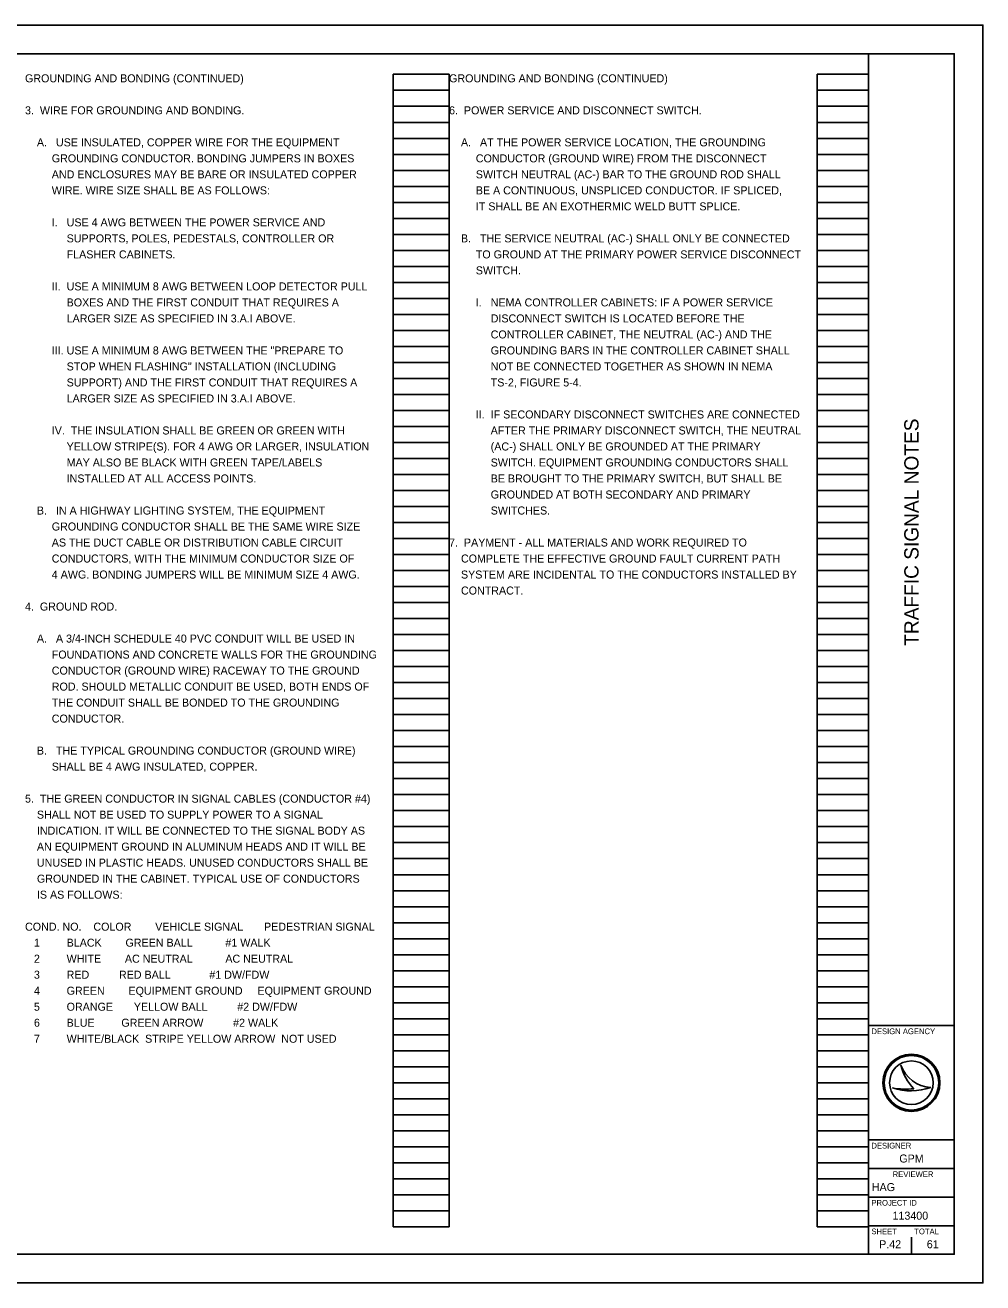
# Model space of a CAD drawing. Extents: x 0 to 34, y 0 to 22.
# Drawn here: x 17.24 to 34, y 0 to 22 of the extents above; entities that cross this region are included whole.
import ezdxf

# ---------------------------------------------------------------- set-up
doc = ezdxf.new("R2010")
doc.units = 0
for name, color, linetype in [('SH_Border', 7, 'Continuous'), ('SH_Cut_Line', 7, 'Continuous'), ('SH_Data', 7, 'Continuous'), ('SH_Text', 7, 'Continuous')]:
    doc.layers.add(name, color=color, linetype=linetype)

msp = doc.modelspace()

# ---------------------------------------------------------------- linework, layer by layer
at = {"layer": 'SH_Border'}
for p, q in [((32, 0.5), (32, 21.5)), ((32, 4.5), (33.5, 4.5)), ((32, 2.5), (33.5, 2.5)), ((32, 2), (33.5, 2)), ((32, 1.5), (33.5, 1.5)), ((32, 1), (33.5, 1))]:
    msp.add_line(p, q, dxfattribs=at)
msp.add_lwpolyline([(1.5, 21.5), (33.5, 21.5), (33.5, 0.5), (1.5, 0.5)], close=True, dxfattribs=at)
at = {"layer": 'SH_Cut_Line'}
msp.add_lwpolyline([(0, 0), (34, 0), (34, 22), (0, 22)], close=True, dxfattribs=at)
at = {"layer": 'SH_Data'}
for p, q in [((23.68, 0.98), (23.68, 21.14)), ((23.68, 21.14), (24.66, 21.14)), ((24.66, 0.98), (24.66, 21.14)), ((31.1, 0.98), (31.1, 21.14)), ((31.1, 21.14), (32, 21.14)), ((32, 0.98), (32, 21.14)), ((23.68, 20.86), (24.66, 20.86)), ((31.1, 20.86), (32, 20.86)), ((23.68, 20.58), (24.66, 20.58)), ((31.1, 20.58), (32, 20.58)), ((23.68, 20.3), (24.66, 20.3)), ((31.1, 20.3), (32, 20.3)), ((23.68, 20.02), (24.66, 20.02)), ((31.1, 20.02), (32, 20.02)), ((23.68, 19.74), (24.66, 19.74)), ((31.1, 19.74), (32, 19.74)), ((23.68, 19.46), (24.66, 19.46)), ((31.1, 19.46), (32, 19.46)), ((23.68, 19.18), (24.66, 19.18)), ((31.1, 19.18), (32, 19.18)), ((23.68, 18.9), (24.66, 18.9)), ((31.1, 18.9), (32, 18.9)), ((23.68, 18.62), (24.66, 18.62)), ((31.1, 18.62), (32, 18.62)), ((23.68, 18.34), (24.66, 18.34)), ((31.1, 18.34), (32, 18.34)), ((23.68, 18.06), (24.66, 18.06)), ((31.1, 18.06), (32, 18.06)), ((23.68, 17.78), (24.66, 17.78)), ((31.1, 17.78), (32, 17.78)), ((23.68, 17.5), (24.66, 17.5)), ((31.1, 17.5), (32, 17.5)), ((23.68, 17.22), (24.66, 17.22)), ((31.1, 17.22), (32, 17.22)), ((23.68, 16.94), (24.66, 16.94)), ((31.1, 16.94), (32, 16.94)), ((23.68, 16.66), (24.66, 16.66)), ((31.1, 16.66), (32, 16.66)), ((23.68, 16.38), (24.66, 16.38)), ((31.1, 16.38), (32, 16.38)), ((23.68, 16.1), (24.66, 16.1)), ((31.1, 16.1), (32, 16.1)), ((23.68, 15.82), (24.66, 15.82)), ((31.1, 15.82), (32, 15.82)), ((23.68, 15.54), (24.66, 15.54)), ((31.1, 15.54), (32, 15.54)), ((23.68, 15.26), (24.66, 15.26)), ((31.1, 15.26), (32, 15.26)), ((23.68, 14.98), (24.66, 14.98)), ((31.1, 14.98), (32, 14.98)), ((23.68, 14.7), (24.66, 14.7)), ((31.1, 14.7), (32, 14.7)), ((23.68, 14.42), (24.66, 14.42)), ((31.1, 14.42), (32, 14.42)), ((23.68, 14.14), (24.66, 14.14)), ((31.1, 14.14), (32, 14.14)), ((23.68, 13.86), (24.66, 13.86)), ((31.1, 13.86), (32, 13.86)), ((23.68, 13.58), (24.66, 13.58)), ((31.1, 13.58), (32, 13.58)), ((23.68, 13.3), (24.66, 13.3)), ((31.1, 13.3), (32, 13.3)), ((23.68, 13.02), (24.66, 13.02)), ((31.1, 13.02), (32, 13.02)), ((23.68, 12.74), (24.66, 12.74)), ((31.1, 12.74), (32, 12.74)), ((23.68, 12.46), (24.66, 12.46)), ((31.1, 12.46), (32, 12.46)), ((23.68, 12.18), (24.66, 12.18)), ((31.1, 12.18), (32, 12.18)), ((23.68, 11.9), (24.66, 11.9)), ((31.1, 11.9), (32, 11.9)), ((23.68, 11.62), (24.66, 11.62)), ((31.1, 11.62), (32, 11.62)), ((23.68, 11.34), (24.66, 11.34)), ((31.1, 11.34), (32, 11.34)), ((23.68, 11.06), (24.66, 11.06)), ((31.1, 11.06), (32, 11.06)), ((23.68, 10.78), (24.66, 10.78)), ((31.1, 10.78), (32, 10.78)), ((23.68, 10.5), (24.66, 10.5)), ((31.1, 10.5), (32, 10.5)), ((23.68, 10.22), (24.66, 10.22)), ((31.1, 10.22), (32, 10.22)), ((23.68, 9.94), (24.66, 9.94)), ((31.1, 9.94), (32, 9.94)), ((23.68, 9.66), (24.66, 9.66)), ((31.1, 9.66), (32, 9.66)), ((23.68, 9.38), (24.66, 9.38)), ((31.1, 9.38), (32, 9.38)), ((23.68, 9.1), (24.66, 9.1)), ((31.1, 9.1), (32, 9.1)), ((23.68, 8.82), (24.66, 8.82)), ((31.1, 8.82), (32, 8.82)), ((23.68, 8.54), (24.66, 8.54)), ((31.1, 8.54), (32, 8.54)), ((23.68, 8.26), (24.66, 8.26)), ((31.1, 8.26), (32, 8.26)), ((23.68, 7.98), (24.66, 7.98)), ((31.1, 7.98), (32, 7.98)), ((23.68, 7.7), (24.66, 7.7)), ((31.1, 7.7), (32, 7.7)), ((23.68, 7.42), (24.66, 7.42)), ((31.1, 7.42), (32, 7.42)), ((23.68, 7.14), (24.66, 7.14)), ((31.1, 7.14), (32, 7.14)), ((23.68, 6.86), (24.66, 6.86)), ((31.1, 6.86), (32, 6.86)), ((23.68, 6.58), (24.66, 6.58)), ((31.1, 6.58), (32, 6.58)), ((23.68, 6.3), (24.66, 6.3)), ((31.1, 6.3), (32, 6.3)), ((23.68, 6.02), (24.66, 6.02)), ((31.1, 6.02), (32, 6.02)), ((23.68, 5.74), (24.66, 5.74)), ((31.1, 5.74), (32, 5.74)), ((23.68, 5.46), (24.66, 5.46)), ((31.1, 5.46), (32, 5.46)), ((23.68, 5.18), (24.66, 5.18)), ((31.1, 5.18), (32, 5.18)), ((23.68, 4.9), (24.66, 4.9)), ((31.1, 4.9), (32, 4.9)), ((23.68, 4.62), (24.66, 4.62)), ((31.1, 4.62), (32, 4.62)), ((23.68, 4.34), (24.66, 4.34)), ((31.1, 4.34), (32, 4.34)), ((23.68, 4.06), (24.66, 4.06)), ((31.1, 4.06), (32, 4.06)), ((23.68, 3.78), (24.66, 3.78)), ((31.1, 3.78), (32, 3.78)), ((32.567, 3.81), (32.567, 3.81)), ((23.68, 3.5), (24.66, 3.5)), ((31.1, 3.5), (32, 3.5)), ((32.417, 3.41), (32.417, 3.41)), ((32.75, 3.5), (32.75, 3.5)), ((33.087, 3.419), (33.087, 3.419)), ((23.68, 3.22), (24.66, 3.22)), ((31.1, 3.22), (32, 3.22)), ((23.68, 2.94), (24.66, 2.94)), ((31.1, 2.94), (32, 2.94)), ((23.68, 2.66), (24.66, 2.66)), ((31.1, 2.66), (32, 2.66)), ((23.68, 2.38), (24.66, 2.38)), ((31.1, 2.38), (32, 2.38)), ((23.68, 2.1), (24.66, 2.1)), ((31.1, 2.1), (32, 2.1)), ((23.68, 1.82), (24.66, 1.82)), ((31.1, 1.82), (32, 1.82)), ((23.68, 1.54), (24.66, 1.54)), ((31.1, 1.54), (32, 1.54)), ((23.68, 1.26), (24.66, 1.26)), ((31.1, 1.26), (32, 1.26)), ((23.68, 0.98), (24.66, 0.98)), ((31.1, 0.98), (32, 0.98)), ((32.375, 0.675), (32.375, 0.675)), ((32.75, 0.5), (32.75, 0.8))]:
    msp.add_line(p, q, dxfattribs=at)
for radius in [0.5, 0.477, 0.477, 0.382]:
    msp.add_circle((32.75, 3.5), radius, dxfattribs=at)
for centre, radius, start, end in [((33.116, 3.998), 0.58, 198.9257, 198.9319), ((33.347, 3.97), 0.796, 191.6379, 191.6421), ((33.116, 3.998), 0.58, 198.9319, 267.1657), ((33.347, 3.97), 0.796, 191.6421, 226.0947), ((32.739, 4.37), 1.013, 251.4576, 290.0832), ((32.648, 4.654), 1.266, 259.4964, 259.4995), ((32.739, 4.37), 1.013, 251.4527, 251.4576), ((32.648, 4.654), 1.266, 259.4995, 276.6672)]:
    msp.add_arc(centre, radius, start, end, dxfattribs=at)

# ---------------------------------------------------------------- texts
msp.add_text('TRAFFIC SIGNAL NOTES', height=0.25, rotation=90, dxfattribs=at).set_placement((32.875, 11.144))
for s, height, p in [('DESIGN AGENCY', 0.1, (32.05, 4.35)), ('DESIGNER', 0.1, (32.05, 2.35)), ('GPM', 0.14, (32.538, 2.105)), ('REVIEWER', 0.1, (32.422, 1.85)), ('HAG', 0.14, (32.057, 1.605)), ('PROJECT ID', 0.1, (32.05, 1.35)), ('113400', 0.14, (32.419, 1.105)), ('SHEET', 0.1, (32.05, 0.85)), ('TOTAL', 0.1, (32.8, 0.85)), ('P.42', 0.14, (32.185, 0.605)), ('61', 0.14, (33.019, 0.605))]:
    msp.add_text(s, height=height, dxfattribs=at).set_placement(p)
at = {"layer": 'SH_Text'}
for s, p in [('GROUNDING AND BONDING (CONTINUED)', (17.24, 21)), ('GROUNDING AND BONDING (CONTINUED)', (24.66, 21)), ('3.  WIRE FOR GROUNDING AND BONDING.', (17.24, 20.44)), ('6.  POWER SERVICE AND DISCONNECT SWITCH.', (24.66, 20.44)), ('    A.   USE INSULATED, COPPER WIRE FOR THE EQUIPMENT', (17.24, 19.88)), ('    A.   AT THE POWER SERVICE LOCATION, THE GROUNDING', (24.66, 19.88)), ('         GROUNDING CONDUCTOR. BONDING JUMPERS IN BOXES', (17.24, 19.6)), ('         CONDUCTOR (GROUND WIRE) FROM THE DISCONNECT', (24.66, 19.6)), ('         AND ENCLOSURES MAY BE BARE OR INSULATED COPPER', (17.24, 19.32)), ('         SWITCH NEUTRAL (AC-) BAR TO THE GROUND ROD SHALL', (24.66, 19.32)), ('         WIRE. WIRE SIZE SHALL BE AS FOLLOWS:', (17.24, 19.04)), ('         BE A CONTINUOUS, UNSPLICED CONDUCTOR. IF SPLICED,', (24.66, 19.04)), ('         IT SHALL BE AN EXOTHERMIC WELD BUTT SPLICE.', (24.66, 18.76)), ('         I.   USE 4 AWG BETWEEN THE POWER SERVICE AND', (17.24, 18.48)), ('              SUPPORTS, POLES, PEDESTALS, CONTROLLER OR', (17.24, 18.2)), ('    B.   THE SERVICE NEUTRAL (AC-) SHALL ONLY BE CONNECTED', (24.66, 18.2)), ('              FLASHER CABINETS.', (17.24, 17.92)), ('         TO GROUND AT THE PRIMARY POWER SERVICE DISCONNECT', (24.66, 17.92)), ('         SWITCH.', (24.66, 17.64)), ('         II.  USE A MINIMUM 8 AWG BETWEEN LOOP DETECTOR PULL', (17.24, 17.36)), ('              BOXES AND THE FIRST CONDUIT THAT REQUIRES A', (17.24, 17.08)), ('         I.   NEMA CONTROLLER CABINETS: IF A POWER SERVICE', (24.66, 17.08)), ('              LARGER SIZE AS SPECIFIED IN 3.A.I ABOVE.', (17.24, 16.8)), ('              DISCONNECT SWITCH IS LOCATED BEFORE THE', (24.66, 16.8)), ('              CONTROLLER CABINET, THE NEUTRAL (AC-) AND THE', (24.66, 16.52)), ('         III. USE A MINIMUM 8 AWG BETWEEN THE "PREPARE TO', (17.24, 16.24)), ('              GROUNDING BARS IN THE CONTROLLER CABINET SHALL', (24.66, 16.24)), ('              STOP WHEN FLASHING" INSTALLATION (INCLUDING', (17.24, 15.96)), ('              NOT BE CONNECTED TOGETHER AS SHOWN IN NEMA', (24.66, 15.96)), ('              SUPPORT) AND THE FIRST CONDUIT THAT REQUIRES A', (17.24, 15.68)), ('              TS-2, FIGURE 5-4.', (24.66, 15.68)), ('              LARGER SIZE AS SPECIFIED IN 3.A.I ABOVE.', (17.24, 15.4)), ('         II.  IF SECONDARY DISCONNECT SWITCHES ARE CONNECTED', (24.66, 15.12)), ('         IV.  THE INSULATION SHALL BE GREEN OR GREEN WITH', (17.24, 14.84)), ('              AFTER THE PRIMARY DISCONNECT SWITCH, THE NEUTRAL', (24.66, 14.84)), ('              YELLOW STRIPE(S). FOR 4 AWG OR LARGER, INSULATION', (17.24, 14.56)), ('              (AC-) SHALL ONLY BE GROUNDED AT THE PRIMARY', (24.66, 14.56)), ('              MAY ALSO BE BLACK WITH GREEN TAPE/LABELS', (17.24, 14.28)), ('              SWITCH. EQUIPMENT GROUNDING CONDUCTORS SHALL', (24.66, 14.28)), ('              INSTALLED AT ALL ACCESS POINTS.', (17.24, 14)), ('              BE BROUGHT TO THE PRIMARY SWITCH, BUT SHALL BE', (24.66, 14)), ('              GROUNDED AT BOTH SECONDARY AND PRIMARY', (24.66, 13.72)), ('    B.   IN A HIGHWAY LIGHTING SYSTEM, THE EQUIPMENT', (17.24, 13.44)), ('              SWITCHES.', (24.66, 13.44)), ('         GROUNDING CONDUCTOR SHALL BE THE SAME WIRE SIZE', (17.24, 13.16)), ('         AS THE DUCT CABLE OR DISTRIBUTION CABLE CIRCUIT', (17.24, 12.88)), ('7.  PAYMENT - ALL MATERIALS AND WORK REQUIRED TO', (24.66, 12.88)), ('         CONDUCTORS, WITH THE MINIMUM CONDUCTOR SIZE OF', (17.24, 12.6)), ('    COMPLETE THE EFFECTIVE GROUND FAULT CURRENT PATH', (24.66, 12.6)), ('         4 AWG. BONDING JUMPERS WILL BE MINIMUM SIZE 4 AWG.', (17.24, 12.32)), ('    SYSTEM ARE INCIDENTAL TO THE CONDUCTORS INSTALLED BY', (24.66, 12.32)), ('    CONTRACT.', (24.66, 12.04)), ('4.  GROUND ROD.', (17.24, 11.76)), ('    A.   A 3/4-INCH SCHEDULE 40 PVC CONDUIT WILL BE USED IN', (17.24, 11.2)), ('         FOUNDATIONS AND CONCRETE WALLS FOR THE GROUNDING', (17.24, 10.92)), ('         CONDUCTOR (GROUND WIRE) RACEWAY TO THE GROUND', (17.24, 10.64)), ('         ROD. SHOULD METALLIC CONDUIT BE USED, BOTH ENDS OF', (17.24, 10.36)), ('         THE CONDUIT SHALL BE BONDED TO THE GROUNDING', (17.24, 10.08)), ('         CONDUCTOR.', (17.24, 9.8)), ('    B.   THE TYPICAL GROUNDING CONDUCTOR (GROUND WIRE)', (17.24, 9.24)), ('         SHALL BE 4 AWG INSULATED, COPPER.', (17.24, 8.96)), ('5.  THE GREEN CONDUCTOR IN SIGNAL CABLES (CONDUCTOR #4)', (17.24, 8.4)), ('    SHALL NOT BE USED TO SUPPLY POWER TO A SIGNAL', (17.24, 8.12)), ('    INDICATION. IT WILL BE CONNECTED TO THE SIGNAL BODY AS', (17.24, 7.84)), ('    AN EQUIPMENT GROUND IN ALUMINUM HEADS AND IT WILL BE', (17.24, 7.56)), ('    UNUSED IN PLASTIC HEADS. UNUSED CONDUCTORS SHALL BE', (17.24, 7.28)), ('    GROUNDED IN THE CABINET. TYPICAL USE OF CONDUCTORS', (17.24, 7)), ('    IS AS FOLLOWS:', (17.24, 6.72)), ('COND. NO.    COLOR        VEHICLE SIGNAL       PEDESTRIAN SIGNAL', (17.24, 6.16)), ('   1         BLACK        GREEN BALL           #1 WALK', (17.24, 5.88)), ('   2         WHITE        AC NEUTRAL           AC NEUTRAL', (17.24, 5.6)), ('   3         RED          RED BALL             #1 DW/FDW', (17.24, 5.32)), ('   4         GREEN        EQUIPMENT GROUND     EQUIPMENT GROUND', (17.24, 5.04)), ('   5         ORANGE       YELLOW BALL          #2 DW/FDW', (17.24, 4.76)), ('   6         BLUE         GREEN ARROW          #2 WALK', (17.24, 4.48)), ('   7         WHITE/BLACK  STRIPE YELLOW ARROW  NOT USED', (17.24, 4.2))]:
    msp.add_text(s, height=0.14, dxfattribs=at).set_placement(p)

doc.saveas('drawing.dxf')
